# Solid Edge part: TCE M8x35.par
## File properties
Title: 1320800099
Subject: Vite TCEI M8x35
Author: g_deluca
Template: RBuno.par
Last saved by: g_deluca
Revision: 13
Application: Solid Edge
Material: Classe 8.8
Tipo di contenuto documento: 0
Company: EFFEBI S.p.A.
Codice: /
Indice rev.: Rev.
Data rev.: Data rev.
Firma rev.: Firma rev.
Descrizione rev.: Descrizione rev.
Densità: 7860.000 kg/m^3
Precisione: 0.99
Document Number: UNI 5931
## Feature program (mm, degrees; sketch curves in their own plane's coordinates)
sketch for "unnamed Protrusion 1" plane through (0, 0, 0) normal (0, 0, 1) x-axis (1, 0, 0)
extrude "unnamed Protrusion 1" add finite 8 along +normal
sketch for "ExtrudedProtrusion_3" plane through (0, 0, 0) normal (0, 0, -1) x-axis (1, 0, 0)
extrude "ExtrudedProtrusion_3" add finite 35 along +normal
sketch for "ExtrudedCutout_1" plane through (0, 0, 8) normal (0, 0, 1) x-axis (1, 0, 0)
  line (-3, 1.7321) -> (-3, -1.7321)
  line (0, -3.4641) -> (-3, -1.7321)
  line (3, -1.7321) -> (0, -3.4641)
  line (3, 1.7321) -> (3, -1.7321)
  line (3, 1.7321) -> (0, 3.4641)
  line (0, 3.4641) -> (-3, 1.7321)
extrude "ExtrudedCutout_1" cut finite 6.35 along -normal
thread "unnamed Thread 1"
fillet "Rotondo_2" radius 0.5
fillet "Rotondo_3" radius 0.5
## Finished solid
Body 1: solid body, 20 faces, 36 edges, 18 vertices.
  Faces by surface: plane 10, cylinder 8, torus 2
  Edges by curve: line 24, circle 6, ellipse 6
Bounding box of the edges (mm; curved faces can reach further): 13.000 x 13.000 x 43.000, from (-6.5, -6.5, -35) to (6.5, 6.5, 8).
Cylindrical faces by radius (mm): R0.5 x6, R4 x1, R6.5 x1
Toroidal faces (ring radius, tube radius in mm): R3.5 r0.5 x1, R6 r0.5 x1
Planar faces by outward normal: +x 1, +z 2, -x 1, -z 2, oblique 4
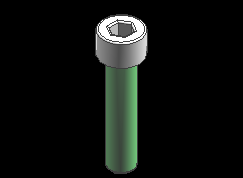
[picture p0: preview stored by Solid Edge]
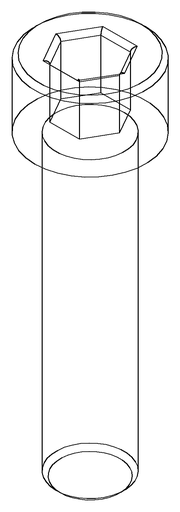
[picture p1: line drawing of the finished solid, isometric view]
